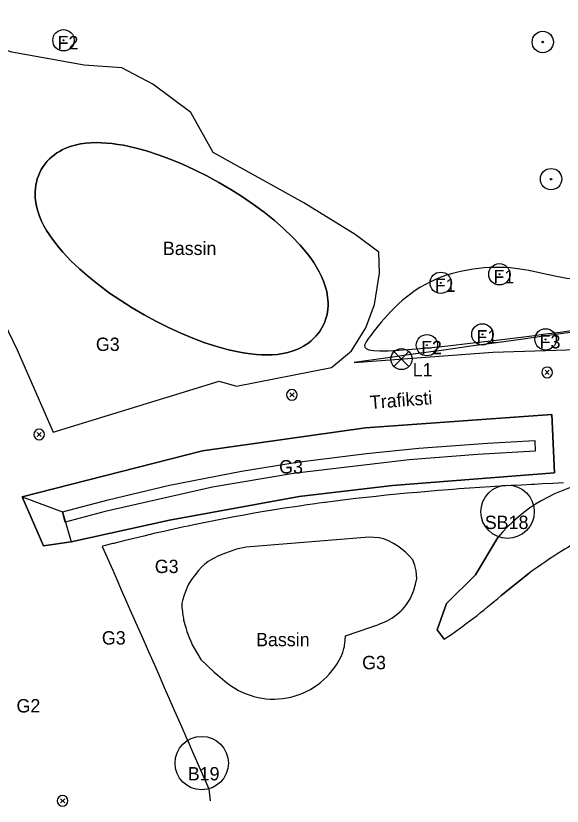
# Model space of a CAD drawing. Extents: x 0 to 512122, y 0 to 6212554.
# Drawn here: x 511594.1 to 511645.3, y 6211524.5 to 6211598.5 of the extents above; entities that cross this region are included whole.
import ezdxf

# ---------------------------------------------------------------- set-up
doc = ezdxf.new("R2010")
doc.units = 0
for name, color, linetype in [('_G3S_Slået græsser', 7, 'Continuous'), ('_lights', 7, 'Continuous'), ('_Låge L1', 7, 'Continuous'), ('_ny fruit trees', 7, 'Continuous'), ('_S5_spansk kørvel', 7, 'Continuous'), ('_solitaire tree_ K3', 7, 'Continuous'), ('Bassin - bottom', 7, 'Continuous'), ('L40 jord udlagt muld og grøft', 7, 'Continuous'), ('MatrikelnummerMaster', 7, 'Continuous'), ('TV_U_AFM_Symbl_Gul', 7, 'Continuous'), ('TV_U_LYS_Mastenummer', 7, 'Continuous'), ('TV_U_LYS_Nyx330-Trafiksti-x2', 7, 'Continuous')]:
    doc.layers.add(name, color=color, linetype=linetype)

msp = doc.modelspace()

# ---------------------------------------------------------------- linework, layer by layer
at = {"layer": '_G3S_Slået græsser'}
msp.add_arc((511599.726, 6211577.452), 18.295, 247.4746, 247.4746, dxfattribs=at)
at = {"layer": '_lights'}
for p, q in [((511643.676, 6211565.306), (511644.07, 6211564.912)), ((511644.074, 6211565.31), (511643.68, 6211564.916)), ((511619.777, 6211563.208), (511620.171, 6211562.814)), ((511620.175, 6211563.212), (511619.781, 6211562.818)), ((511596.107, 6211559.493), (511596.501, 6211559.099)), ((511596.505, 6211559.497), (511596.111, 6211559.103)), ((511598.302, 6211525.182), (511598.696, 6211524.787)), ((511598.7, 6211525.186), (511598.306, 6211524.791))]:
    msp.add_line(p, q, dxfattribs=at)
for centre, start, end in [((511643.873, 6211565.109), 315.56363, 315), ((511643.873, 6211565.109), 315, 315.56363), ((511619.974, 6211563.011), 315.56363, 315), ((511619.974, 6211563.011), 315, 315.56363), ((511596.304, 6211559.296), 315.56363, 315), ((511596.304, 6211559.296), 315, 315.56363), ((511598.499, 6211524.985), 315.56363, 315), ((511598.499, 6211524.985), 315, 315.56363)]:
    msp.add_arc(centre, 0.5, start, end, dxfattribs=at)
at = {"layer": '_Låge L1'}
for p, q in [((511630.931, 6211567.056), (511629.533, 6211565.657)), ((511629.533, 6211567.056), (511630.931, 6211565.657))]:
    msp.add_line(p, q, dxfattribs=at)
msp.add_circle((511630.232, 6211566.357), 0.989, dxfattribs=at)
at = {"layer": '_ny fruit trees'}
for centre, radius in [((511598.584, 6211596.217), 1), ((511598.584, 6211596.217), 0.0426), ((511639.404, 6211574.301), 1), ((511633.913, 6211573.5), 1), ((511639.404, 6211574.301), 0.0426), ((511633.913, 6211573.5), 0.0426), ((511637.808, 6211568.671), 1), ((511643.725, 6211568.205), 1), ((511632.621, 6211567.661), 1), ((511637.808, 6211568.671), 0.0426), ((511643.725, 6211568.205), 0.0426), ((511632.621, 6211567.661), 0.0426)]:
    msp.add_circle(centre, radius, dxfattribs=at)
at = {"layer": '_S5_spansk kørvel'}
for p, q in [((511642.201, 6211546.3), (511639.578, 6211544.224)), ((511639.578, 6211544.224), (511642.201, 6211546.3)), ((511634.245, 6211540.133), (511633.574, 6211541.015))]:
    msp.add_line(p, q, dxfattribs=at)
for points in [[(511633.574, 6211541.015), (511634.452, 6211543.482), (511637.167, 6211546.142), (511639.245, 6211549.64)], [(511639.245, 6211549.64), (511637.167, 6211546.142), (511634.452, 6211543.482), (511633.574, 6211541.015), (511634.245, 6211540.133)]]:
    msp.add_lwpolyline(points, dxfattribs=at)
for centre, radius, start, end in [((511650.867, 6211540.016), 15.09, 99.23851, 140.37499), ((511650.867, 6211540.016), 15.09, 99.23851, 140.37499), ((511666.214, 6211514.311), 39.999, 118.0529, 121.55181), ((511666.214, 6211514.311), 39.999, 121.55181, 126.89348), ((511666.214, 6211514.311), 39.999, 121.55181, 126.89348), ((511603.117, 6211586.232), 55.624, 304.02971, 310.95709), ((511603.117, 6211586.232), 55.624, 304.02971, 310.95709)]:
    msp.add_arc(centre, radius, start, end, dxfattribs=at)
at = {"layer": '_solitaire tree_ K3'}
for centre, radius in [((511643.468, 6211596.054), 1), ((511643.468, 6211596.054), 0.0703), ((511644.247, 6211583.21), 1), ((511644.247, 6211583.21), 0.0703)]:
    msp.add_circle(centre, radius, dxfattribs=at)
at = {"layer": 'Bassin - bottom'}
for points in [[(511622.779, 6211569.272), (511622.926, 6211569.557), (511623.051, 6211569.849), (511623.155, 6211570.146), (511623.236, 6211570.445), (511623.295, 6211570.744), (511623.335, 6211571.039), (511623.356, 6211571.33), (511623.359, 6211571.615), (511623.347, 6211571.893), (511623.321, 6211572.164), (511623.232, 6211572.685), (511623.103, 6211573.18), (511622.94, 6211573.652), (511622.748, 6211574.106), (511622.53, 6211574.544), (511622.289, 6211574.972), (511622.025, 6211575.391), (511621.74, 6211575.804), (511621.433, 6211576.212), (511621.105, 6211576.618), (511620.756, 6211577.022), (511620.003, 6211577.818), (511619.185, 6211578.598), (511618.305, 6211579.363), (511617.368, 6211580.111), (511616.379, 6211580.841), (511615.342, 6211581.55), (511614.262, 6211582.234), (511613.144, 6211582.89), (511612.005, 6211583.509), (511610.861, 6211584.08), (511609.719, 6211584.602), (511608.583, 6211585.072), (511607.458, 6211585.488), (511606.349, 6211585.847), (511605.259, 6211586.145), (511604.188, 6211586.378), (511603.662, 6211586.468), (511603.145, 6211586.539), (511602.637, 6211586.591), (511602.136, 6211586.622), (511601.641, 6211586.632), (511601.15, 6211586.618), (511600.662, 6211586.578), (511600.175, 6211586.508), (511599.686, 6211586.404), (511599.196, 6211586.259), (511598.703, 6211586.066), (511598.458, 6211585.948), (511598.213, 6211585.815), (511597.971, 6211585.665), (511597.733, 6211585.497), (511597.5, 6211585.31), (511597.276, 6211585.105), (511597.061, 6211584.881), (511596.86, 6211584.64), (511596.675, 6211584.381), (511596.507, 6211584.108), (511596.36, 6211583.824), (511596.234, 6211583.531), (511596.131, 6211583.234), (511596.05, 6211582.935), (511595.99, 6211582.637), (511595.951, 6211582.341), (511595.93, 6211582.051), (511595.927, 6211581.766), (511595.939, 6211581.488), (511595.965, 6211581.216), (511596.054, 6211580.695), (511596.183, 6211580.2), (511596.346, 6211579.728), (511596.538, 6211579.275), (511596.756, 6211578.836), (511596.997, 6211578.409), (511597.261, 6211577.99), (511597.546, 6211577.577), (511597.853, 6211577.168), (511598.181, 6211576.763), (511598.53, 6211576.359), (511599.283, 6211575.562), (511600.101, 6211574.782), (511600.981, 6211574.018), (511601.918, 6211573.269), (511602.907, 6211572.54), (511603.944, 6211571.831), (511605.024, 6211571.147), (511606.142, 6211570.49), (511607.281, 6211569.872), (511608.425, 6211569.301), (511609.567, 6211568.779), (511610.703, 6211568.309), (511611.827, 6211567.893), (511612.936, 6211567.534), (511614.027, 6211567.236), (511615.098, 6211567.003), (511615.624, 6211566.912), (511616.141, 6211566.841), (511616.649, 6211566.789), (511617.15, 6211566.758), (511617.645, 6211566.749), (511618.136, 6211566.763), (511618.624, 6211566.803), (511619.111, 6211566.873), (511619.6, 6211566.977), (511620.09, 6211567.121), (511620.582, 6211567.315), (511620.828, 6211567.432), (511621.073, 6211567.566), (511621.315, 6211567.716), (511621.553, 6211567.884), (511621.786, 6211568.07), (511622.01, 6211568.275), (511622.224, 6211568.499), (511622.426, 6211568.741), (511622.611, 6211568.999)], [(511622.611, 6211568.999), (511622.426, 6211568.741), (511622.224, 6211568.499), (511622.01, 6211568.275), (511621.786, 6211568.07), (511621.553, 6211567.884), (511621.315, 6211567.716), (511621.073, 6211567.566), (511620.828, 6211567.432), (511620.582, 6211567.315), (511620.09, 6211567.121), (511619.6, 6211566.977), (511619.111, 6211566.873), (511618.624, 6211566.803), (511618.136, 6211566.763), (511617.645, 6211566.749), (511617.15, 6211566.758), (511616.649, 6211566.789), (511616.141, 6211566.841), (511615.624, 6211566.912), (511615.098, 6211567.003), (511614.027, 6211567.236), (511612.936, 6211567.534), (511611.827, 6211567.893), (511610.703, 6211568.309), (511609.567, 6211568.779), (511608.425, 6211569.301), (511607.281, 6211569.872), (511606.142, 6211570.49), (511605.024, 6211571.147), (511603.944, 6211571.831), (511602.907, 6211572.54), (511601.918, 6211573.269), (511600.981, 6211574.018), (511600.101, 6211574.782), (511599.283, 6211575.562), (511598.53, 6211576.359), (511598.181, 6211576.763), (511597.853, 6211577.168), (511597.546, 6211577.577), (511597.261, 6211577.99), (511596.997, 6211578.409), (511596.756, 6211578.836), (511596.538, 6211579.275), (511596.346, 6211579.728), (511596.183, 6211580.2), (511596.054, 6211580.695), (511595.965, 6211581.216), (511595.939, 6211581.488), (511595.927, 6211581.766), (511595.93, 6211582.051), (511595.951, 6211582.341), (511595.99, 6211582.637), (511596.05, 6211582.935), (511596.131, 6211583.234), (511596.234, 6211583.531), (511596.36, 6211583.824), (511596.507, 6211584.108), (511596.675, 6211584.381), (511596.86, 6211584.64), (511597.061, 6211584.881), (511597.276, 6211585.105), (511597.5, 6211585.31), (511597.733, 6211585.497), (511597.971, 6211585.665), (511598.213, 6211585.815), (511598.458, 6211585.948), (511598.703, 6211586.066), (511599.196, 6211586.259), (511599.686, 6211586.404), (511600.175, 6211586.508), (511600.662, 6211586.578), (511601.15, 6211586.618), (511601.641, 6211586.632), (511602.136, 6211586.622), (511602.637, 6211586.591), (511603.145, 6211586.539), (511603.662, 6211586.468), (511604.188, 6211586.378), (511605.259, 6211586.145), (511606.349, 6211585.847), (511607.458, 6211585.488), (511608.583, 6211585.072), (511609.719, 6211584.602), (511610.861, 6211584.08), (511612.005, 6211583.509), (511613.144, 6211582.89), (511614.262, 6211582.234), (511615.342, 6211581.55), (511616.379, 6211580.841), (511617.368, 6211580.111), (511618.305, 6211579.363), (511619.185, 6211578.598), (511620.003, 6211577.818), (511620.756, 6211577.022), (511621.105, 6211576.618), (511621.433, 6211576.212), (511621.74, 6211575.804), (511622.025, 6211575.391), (511622.289, 6211574.972), (511622.53, 6211574.544), (511622.748, 6211574.106), (511622.94, 6211573.652), (511623.103, 6211573.18), (511623.232, 6211572.685), (511623.321, 6211572.164), (511623.347, 6211571.893), (511623.359, 6211571.615), (511623.356, 6211571.33), (511623.335, 6211571.039), (511623.295, 6211570.744), (511623.236, 6211570.445), (511623.155, 6211570.146), (511623.051, 6211569.849), (511622.926, 6211569.557), (511622.779, 6211569.272)]]:
    msp.add_lwpolyline(points, close=True, dxfattribs=at)
msp.add_lwpolyline([(511624.73, 6211538.877), (511624.842, 6211539.244), (511624.869, 6211539.338), (511624.889, 6211539.43), (511624.905, 6211539.508), (511624.964, 6211540.04), (511625.004, 6211540.455), (511627.353, 6211541.257), (511627.616, 6211541.345), (511627.924, 6211541.452), (511628.095, 6211541.514), (511628.276, 6211541.584), (511628.468, 6211541.663), (511628.669, 6211541.753), (511628.881, 6211541.856), (511629.103, 6211541.974), (511629.332, 6211542.109), (511629.569, 6211542.266), (511629.81, 6211542.445), (511630.052, 6211542.65), (511630.173, 6211542.763), (511630.203, 6211542.793), (511630.232, 6211542.822), (511630.291, 6211542.882), (511630.512, 6211543.129), (511630.711, 6211543.384), (511630.888, 6211543.646), (511631.045, 6211543.912), (511631.183, 6211544.181), (511631.302, 6211544.452), (511631.404, 6211544.724), (511631.56, 6211545.27), (511631.657, 6211545.816), (511631.606, 6211546.521), (511631.49, 6211547.039), (511631.296, 6211547.549), (511630.962, 6211547.942), (511630.606, 6211548.278), (511630.255, 6211548.565), (511629.885, 6211548.842), (511629.473, 6211549.102), (511629.025, 6211549.341), (511628.578, 6211549.509), (511628.131, 6211549.615), (511627.222, 6211549.679), (511615.699, 6211548.756), (511614.776, 6211548.557), (511613.754, 6211548.195), (511613.105, 6211547.927), (511612.626, 6211547.682), (511612.344, 6211547.528), (511612.13, 6211547.387), (511611.942, 6211547.254), (511611.826, 6211547.153), (511611.495, 6211546.862), (511611.22, 6211546.545), (511610.901, 6211546.167), (511610.577, 6211545.717), (511610.266, 6211545.216), (511610.059, 6211544.75), (511609.882, 6211544.263), (511609.737, 6211543.758), (511609.68, 6211543.498), (511609.671, 6211543.387), (511609.665, 6211543.304), (511609.661, 6211543.209), (511609.661, 6211543.167), (511609.664, 6211543.117), (511609.668, 6211543.076), (511609.683, 6211542.924), (511609.76, 6211542.344), (511609.807, 6211542.101), (511609.835, 6211541.95), (511609.891, 6211541.724), (511609.949, 6211541.489), (511610.026, 6211541.22), (511610.145, 6211540.852), (511610.203, 6211540.692), (511610.359, 6211540.279), (511610.472, 6211539.99), (511610.569, 6211539.774), (511610.643, 6211539.61), (511610.823, 6211539.269), (511611.43, 6211538.23), (511612.691, 6211537.05), (511613.027, 6211536.748), (511613.69, 6211536.193), (511613.985, 6211535.964), (511614.302, 6211535.738)], dxfattribs=at)
msp.add_arc((511618.253, 6211541.505), 6.99, 235.58513, 337.91976, dxfattribs=at)
at = {"layer": 'L40 jord udlagt muld og grøft'}
msp.add_lwpolyline([(511644.554, 6211555.718), (511644.32, 6211561.18), (511626.88, 6211559.911), (511611.608, 6211557.768), (511594.706, 6211553.463), (511596.723, 6211548.877), (511599.295, 6211549.238), (511608.501, 6211551.262), (511620.658, 6211553.494), (511629.387, 6211554.528), (511644.554, 6211555.718)], dxfattribs=at)
for points in [[(511629.387, 6211554.528), (511620.658, 6211553.494), (511608.501, 6211551.262), (511599.295, 6211549.238), (511596.723, 6211548.877), (511594.706, 6211553.463), (511611.608, 6211557.768), (511626.88, 6211559.911), (511644.32, 6211561.18), (511644.554, 6211555.718)], [(511642.723, 6211558.735), (511642.766, 6211557.736), (511637.358, 6211557.423), (511630.961, 6211556.922), (511620.122, 6211555.646), (511612.548, 6211554.354), (511602.488, 6211552.089), (511598.754, 6211551.084), (511598.483, 6211552.047), (511602.759, 6211553.19), (511608.504, 6211554.543), (511615.259, 6211555.872), (511620.463, 6211556.706), (511626.953, 6211557.526), (511631.866, 6211558.006), (511638.281, 6211558.485)], [(511594.706, 6211553.463), (511598.483, 6211552.047), (511599.295, 6211549.238), (511596.723, 6211548.877)]]:
    msp.add_lwpolyline(points, close=True, dxfattribs=at)
at = {"layer": 'MatrikelnummerMaster'}
msp.add_lwpolyline([(511625.811, 6211566.048), (511638.798, 6211567), (511668.377, 6211567.95), (511675.766, 6211569.152), (511678.237, 6211569.935), (511683.129, 6211571.5), (511686.511, 6211572.95), (511689.962, 6211574.907)], dxfattribs=at)
msp.add_open_spline([(511689.962, 6211574.907), (511677.385, 6211580.148), (511666.763, 6211577.81), (511661.475, 6211574.432), (511646.361, 6211573.006), (511641.114, 6211575.532), (511631.762, 6211574.259), (511626.338, 6211567.388), (511625.811, 6211566.048), (511689.962, 6211574.907), (511625.811, 6211566.048)], degree=3, dxfattribs=at)
at = {"layer": 'TV_U_LYS_Mastenummer'}
for centre in [(511640.17, 6211552.062), (511611.526, 6211528.518)]:
    msp.add_circle(centre, 2.5, dxfattribs=at)
at = {"layer": 'TV_U_LYS_Nyx330-Trafiksti-x2'}
msp.add_lwpolyline([(511597.627, 6211559.521), (511613.164, 6211564.276), (511614.769, 6211563.81), (511623.675, 6211565.569), (511625.539, 6211567.121), (511626.885, 6211569.294), (511627.713, 6211571.467), (511628.179, 6211574.416), (511628.127, 6211576.382), (511625.901, 6211578.037), (511621.086, 6211580.986), (511612.595, 6211585.694), (511610.513, 6211589.448), (511606.944, 6211592.116), (511604.04, 6211593.64), (511600.519, 6211593.878), (511593.75, 6211595.088), (511580.53, 6211599.309), (511583.207, 6211591.916), (511589.822, 6211576.386), (511594.245, 6211567.212)], close=True, dxfattribs=at)
for points in [[(511645.398, 6211554.755), (511644.415, 6211554.71), (511643.433, 6211554.663), (511642.683, 6211554.626), (511642.452, 6211554.614), (511641.472, 6211554.562), (511640.493, 6211554.508), (511639.516, 6211554.451), (511639.01, 6211554.42), (511638.539, 6211554.391), (511637.564, 6211554.328), (511636.59, 6211554.261), (511635.617, 6211554.192), (511635.354, 6211554.172), (511635.001, 6211554.146), (511634.645, 6211554.119), (511633.675, 6211554.042), (511632.705, 6211553.962), (511631.738, 6211553.878), (511631.715, 6211553.876), (511630.771, 6211553.79), (511629.806, 6211553.697), (511628.842, 6211553.601), (511628.094, 6211553.523), (511627.879, 6211553.501), (511626.918, 6211553.396), (511625.959, 6211553.286), (511625.001, 6211553.172), (511624.494, 6211553.109), (511624.044, 6211553.053), (511623.09, 6211552.929), (511623.033, 6211552.922), (511622.502, 6211552.85), (511622.136, 6211552.8), (511621.185, 6211552.666), (511620.915, 6211552.627), (511620.235, 6211552.527), (511619.285, 6211552.382), (511618.337, 6211552.232), (511617.39, 6211552.076), (511617.347, 6211552.069), (511616.443, 6211551.915), (511615.497, 6211551.749), (511614.553, 6211551.577), (511613.792, 6211551.434), (511613.609, 6211551.4), (511612.666, 6211551.217), (511611.725, 6211551.029), (511611.269, 6211550.936), (511610.784, 6211550.836), (511610.25, 6211550.723), (511609.845, 6211550.637), (511608.907, 6211550.433), (511607.97, 6211550.223), (511607.034, 6211550.009), (511606.725, 6211549.937), (511606.688, 6211549.928), (511606.099, 6211549.788), (511605.166, 6211549.563), (511604.234, 6211549.332), (511603.303, 6211549.096), (511603.218, 6211549.074), (511602.374, 6211548.854), (511602.253, 6211548.823), (511602.213, 6211548.812)], [(511602.213, 6211548.812), (511602.513, 6211548.132), (511602.791, 6211547.498), (511602.887, 6211547.28), (511603.194, 6211546.583), (511603.596, 6211545.667), (511603.999, 6211544.752), (511604.401, 6211543.837), (511604.804, 6211542.921), (511605.206, 6211542.006), (511605.609, 6211541.09), (511606.012, 6211540.175), (511606.414, 6211539.26), (511606.817, 6211538.344), (511607.219, 6211537.429), (511607.528, 6211536.727), (511607.622, 6211536.513), (511608.024, 6211535.598), (511608.427, 6211534.683), (511608.829, 6211533.767), (511609.232, 6211532.852), (511609.634, 6211531.936), (511610.037, 6211531.021), (511610.44, 6211530.106), (511610.459, 6211530.062), (511612.191, 6211526.123)], [(511612.191, 6211526.123), (511612.332, 6211524.978)]]:
    msp.add_lwpolyline(points, dxfattribs=at)

# ---------------------------------------------------------------- texts
at = {"layer": 'TV_U_AFM_Symbl_Gul'}
for s, p in [('F2', (511598.029, 6211595.368)), ('Bassin', (511607.888, 6211576.105)), ('F1', (511638.849, 6211573.453)), ('F1', (511633.359, 6211572.652)), ('F1', (511637.254, 6211567.822)), ('G3', (511601.616, 6211567.12)), ('F3', (511643.17, 6211567.356)), ('F2', (511632.067, 6211566.813)), ('L1', (511631.285, 6211564.732)), ('G3', (511618.778, 6211555.646)), ('SB18', (511638.036, 6211550.443)), ('G3', (511607.133, 6211546.316)), ('G3', (511602.177, 6211539.626)), ('Bassin', (511616.615, 6211539.465)), ('G3', (511626.551, 6211537.312)), ('G2', (511594.184, 6211533.263)), ('B19', (511610.221, 6211526.9))]:
    msp.add_text(s, height=1.25, dxfattribs=at).set_placement(p)
msp.add_text('Trafiksti', height=1.25, rotation=4.48151, dxfattribs=at).set_placement((511627.325, 6211561.673))

doc.saveas('drawing.dxf')
